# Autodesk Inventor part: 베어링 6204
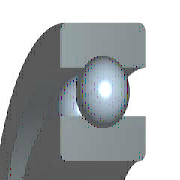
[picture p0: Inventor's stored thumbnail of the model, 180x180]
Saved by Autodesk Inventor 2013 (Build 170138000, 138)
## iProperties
IsCustomPart: 0
Created: 2018-09
Part Number: 베어링 6204
Material: 스테인리스강
Description: 깊은 그루브 볼 베어링
Document SubType Name: Modeling
Standard: KS B 2023
Standards Organization: KS
Language: ko-KR
Size Designation: 6204 - 20 x 47 x 14
Categories: <MemberInstance><Categories><Category DisplayName="샤프트 부품" InternalName="7f7aeb1f-a693-4053-b835-cee3144e0d98" Mnemonic="SHFT"><Category DisplayName="베어링" Inter
Density: 8.08 g/cm^3
Mass: 107.173 g
Surface Area: 87.8912 cm^2
Volume: 13.264 cm^3
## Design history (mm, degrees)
sketch "스케치" dims "d0" = 7.02 (= -0.26 x WD + 0.26 x BD)
  geometry: L1 (3.49, 16.75)-(10.51, 16.75); L2 (7, 16.75)-(7, 13.24); L3 (7, 16.75)-(7, 20.26); L4 (4.392, 14.401)-(0, 14.401); L5 (0, 10)-(14, 10); L6 (4.392, 19.099)-(0, 19.099); L7 (0, 23.5)-(14, 23.5); L8 (14, 10)-(14, 14.401); L9 (9.608, 14.401)-(14, 14.401); L10 (9.608, 19.099)-(14, 19.099); L11 (14, 23.5)-(14, 19.099); L12 (-1.4, 0)-(8.4, 0) reference; L13 (0, -0.3)-(0, 5.3) reference
  constraints: 22 end point, 4 point on line, 2 collinear, 2 perpendicular, 2 symmetric about line, 1 midpoint, 1 parallel, 14 other
  dimensions: "d9" = 20 diameter of L5 L12 (= WD); "d11" = 47 diameter of L7 L12 (= BD); "d12" = 14 distance between parallel lines of L8 L13 (= KB); "d13" = 28.802 diameter of L9 L12 (= 0.326 x BD + 0.674 x WD)
revolve "본체" stored, may be unused: angle "d6" = 90 deg
revolve "볼" stored, may be unused: angle "d7" = 90 deg
pattern_circular "IDS_ARRAYBALL[SIMPL:T]" dims angle "d3" = 360 deg
body "Solid1"
fillet "모깎기1" dims "d1" = 1 (= KRS)
other parameters: "WD" = 20 [user parameter; used in 5 equation terms], "BD" = 47 [user parameter; used in 5 equation terms], "KB" = 14 [user parameter; used in 1 equation term], "KRS" = 1 [user parameter; used in 1 equation term], "d4" = 0, "d5" = 0, "d8" = 0, "d14" = 0, "d15" = 0, "BBA" = 0 [user parameter], "BC0" = 6550000 [user parameter], "BC" = 1.27e+07 [user parameter], "BR" = 23.5 (= 0.5 x BD) [user parameter]
